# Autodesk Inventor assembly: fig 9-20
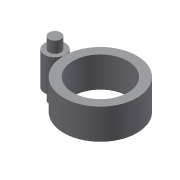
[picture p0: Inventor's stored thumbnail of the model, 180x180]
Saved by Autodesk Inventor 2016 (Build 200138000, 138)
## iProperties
Shininess: 64.0
Length Units: 11269
Angle Units: 11279
Time Units: 11290
Mass Units: 11283
Length Display Precision: 3
Angle Display Precision: 2
Created: 2002-01
Part Number: fig 9-20
Document SubType Name: Assembly
Designer: ***
Density: 0.0
Volumn: 0.0
Area: 0.0
PropertySet Name: Model Information
Control State: 0
Master: False
Checked Out: False
Author: ***
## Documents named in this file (3)
- D:\KAVITA\Autodesk Inventor_ 2016 Project_Kavita\Inventor_Part Files\Inventor_2016_Part\c09_Inv_2016\c09_inv_2016_prt\fig 9-20.iam
- D:\KAVITA\Autodesk Inventor_ 2016 Project_Kavita\Inventor_Part Files\Inventor_2016_Part\c09_Inv_2016\c09_inv_2016_prt\Part8.ipt
- D:\KAVITA\Autodesk Inventor_ 2016 Project_Kavita\Inventor_Part Files\Inventor_2016_Part\c09_Inv_2016\c09_inv_2016_prt\Part9.ipt
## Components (2 placed, 2 different names)
1. Part8:1 — Flush:1
2. Part9:1 — Flush:1
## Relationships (1: Flush 1)
- Flush:1: Part8:1 ↔ Part9:1
